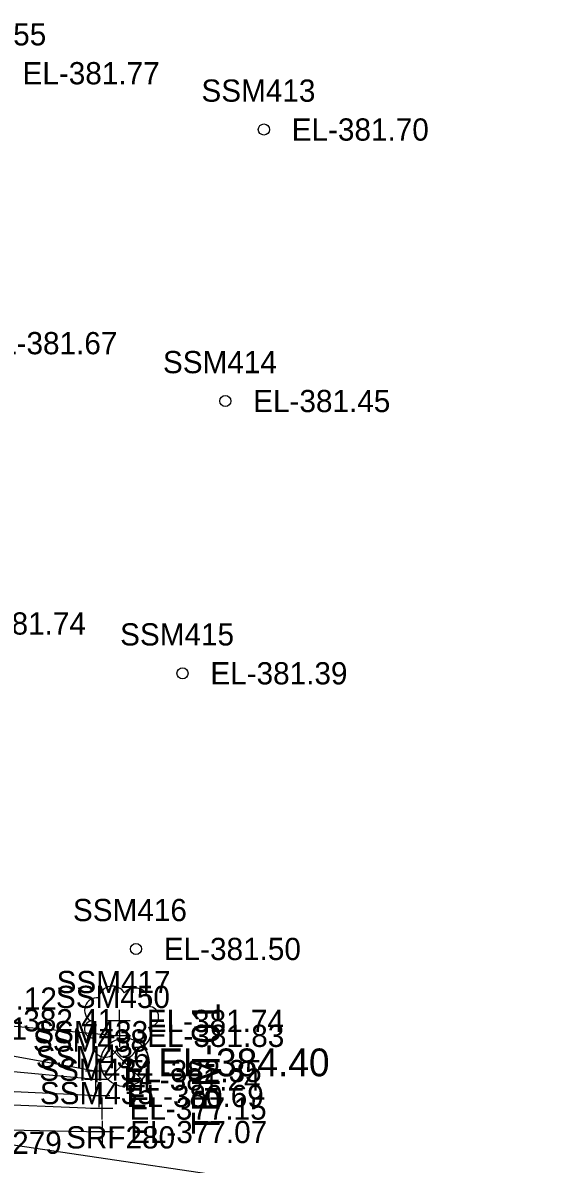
# Model space of a CAD drawing. Extents: x 1189978 to 1314812, y 571533 to 629339.
# Drawn here: x 1217598.3 to 1217693.4, y 620970.5 to 621175.8 of the extents above; entities that cross this region are included whole.
import ezdxf

# ---------------------------------------------------------------- set-up
doc = ezdxf.new("R2010")
doc.units = 0
for name, color, linetype in [('SURVEY - CONTROL - Points - Elevations', 7, 'Continuous'), ('SURVEY - CONTROL with Text', 7, 'Continuous'), ('SURVEY - DTM - Breaklines', 7, 'Continuous'), ('SURVEY - DTM - Breaklines - Points - Elevations', 7, 'Continuous'), ('SURVEY - DTM - Breaklines - Points - Locators', 7, 'Continuous'), ('SURVEY - DTM - Breaklines - Points - Numbers', 7, 'Continuous'), ('SURVEY - DTM - Spot Points - Elevations', 7, 'Continuous'), ('SURVEY - DTM - Spot Points - Locators', 7, 'Continuous'), ('SURVEY - DTM - Spot Points - Point Numbers', 7, 'Continuous'), ('SURVEY - PROPERTY - Property Lines', 7, 'Continuous'), ('SURVEY - VEGETATION - Features - Points - Elevations', 7, 'Continuous'), ('SURVEY - VEGETATION - Features - Points - Locators', 7, 'Continuous'), ('SURVEY - VEGETATION - Features - Points - Numbers', 7, 'Continuous'), ('SURVEY - VEGETATION - Features with Text', 7, 'Continuous')]:
    doc.layers.add(name, color=color, linetype=linetype)

msp = doc.modelspace()

# ---------------------------------------------------------------- linework, layer by layer
at = {"layer": 'SURVEY - CONTROL with Text'}
for p, q in [((1217613.54, 620991.87), (1217616.62, 620988.79)), ((1217616.62, 620988.79), (1217619.7, 620991.88)), ((1217613.55, 620985.73), (1217616.62, 620988.79)), ((1217616.62, 620988.79), (1217619.69, 620985.72))]:
    msp.add_line(p, q, dxfattribs=at)
for points in [[(1217613.55, 620991.86), (1217616.62, 620988.79), (1217613.56, 620985.74), (1217613.31, 620985.99), (1217613.06, 620986.32), (1217612.9, 620986.56), (1217612.73, 620986.88), (1217612.58, 620987.21), (1217612.48, 620987.49), (1217612.41, 620987.75), (1217612.35, 620988.04), (1217612.3, 620988.33), (1217612.28, 620988.59), (1217612.28, 620988.92), (1217612.3, 620989.19), (1217612.32, 620989.43), (1217612.36, 620989.63), (1217612.41, 620989.86), (1217612.49, 620990.13), (1217612.56, 620990.34), (1217612.65, 620990.57), (1217612.83, 620990.92), (1217613.03, 620991.25), (1217613.31, 620991.61)], [(1217619.69, 620991.86), (1217616.62, 620988.79), (1217619.69, 620985.72), (1217619.88, 620985.92), (1217620.11, 620986.19), (1217620.33, 620986.53), (1217620.48, 620986.78), (1217620.66, 620987.18), (1217620.77, 620987.47), (1217620.85, 620987.76), (1217620.9, 620987.99), (1217620.95, 620988.32), (1217620.97, 620988.57), (1217620.98, 620988.88), (1217620.96, 620989.18), (1217620.93, 620989.4), (1217620.89, 620989.67), (1217620.84, 620989.87), (1217620.77, 620990.12), (1217620.64, 620990.48), (1217620.54, 620990.69), (1217620.43, 620990.9), (1217620.22, 620991.25), (1217619.97, 620991.58)]]:
    msp.add_lwpolyline(points, close=True, dxfattribs=at)
msp.add_circle((1217616.63, 620988.8), 4.35, dxfattribs=at)
at = {"layer": 'SURVEY - DTM - Breaklines'}
for points in [[(1217505.41, 621014.24), (1217516.99, 621012.37), (1217518.09, 621005.1), (1217531.46, 621005.05), (1217569.34, 620994.87), (1217611.56, 620987.23)], [(1217508.49, 621010.32), (1217511.86, 621009.77), (1217513.63, 621003.75), (1217524.95, 620995.72), (1217565.78, 620982.39), (1217612.46, 620980.49)], [(1217611.95, 620982.75), (1217567.42, 620984.85), (1217526.98, 620996.85), (1217516.07, 621003.42), (1217514.47, 621008.39), (1217511.86, 621009.77)], [(1217611.37, 620985.73), (1217567.67, 620989.82), (1217529.71, 621000.21), (1217516.95, 621003.56)], [(1217509.63, 621001.3), (1217509.95, 621001.87), (1217523.3, 620992.1), (1217564.68, 620977.32), (1217612.57, 620976.27)]]:
    msp.add_lwpolyline(points, dxfattribs=at)
at = {"layer": 'SURVEY - DTM - Breaklines - Points - Locators'}
for p, q in [((1217611.56, 620989.23), (1217611.56, 620985.23)), ((1217613.56, 620987.23), (1217609.56, 620987.23)), ((1217611.37, 620987.73), (1217611.37, 620983.73)), ((1217613.37, 620985.73), (1217609.37, 620985.73)), ((1217611.95, 620984.75), (1217611.95, 620980.75)), ((1217613.95, 620982.75), (1217609.95, 620982.75)), ((1217612.46, 620982.49), (1217612.46, 620978.49)), ((1217614.46, 620980.49), (1217610.46, 620980.49)), ((1217612.57, 620978.27), (1217612.57, 620974.27)), ((1217614.57, 620976.27), (1217610.57, 620976.27))]:
    msp.add_line(p, q, dxfattribs=at)
at = {"layer": 'SURVEY - DTM - Spot Points - Locators'}
for centre in [(1217641.65, 621156.61), (1217634.72, 621107.77), (1217627.01, 621058.79), (1217618.63, 621009.2)]:
    msp.add_circle(centre, 1, dxfattribs=at)
at = {"layer": 'SURVEY - PROPERTY - Property Lines'}
msp.add_line((1217486.83, 620990.13), (1218812.31, 620794.77), dxfattribs=at)
at = {"layer": 'SURVEY - VEGETATION - Features - Points - Locators'}
for p, q in [((1217615.58, 620998.25), (1217615.58, 620994.25)), ((1217617.58, 620996.25), (1217613.58, 620996.25)), ((1217615.64, 620995.57), (1217615.64, 620991.57)), ((1217617.64, 620993.57), (1217613.64, 620993.57))]:
    msp.add_line(p, q, dxfattribs=at)
at = {"layer": 'SURVEY - VEGETATION - Features with Text'}
msp.add_lwpolyline([(1217602.67, 620954.84), (1217559.6, 620962.1), (1217546.12, 620967.76), (1217551.18, 620997.98), (1217585.03, 620996.37), (1217615.64, 620993.57)], dxfattribs=at)
msp.add_circle((1217615.68, 620996.29), 0.0783, dxfattribs=at)
for centre, radius, start, end in [((1217614.4, 620999.94), 2.56, 31.9683, 169.4925), ((1217618.48, 620999.61), 2.54, 342.8641, 138.7026), ((1217611.62, 620998.18), 2.24, 82.9155, 239.7044), ((1217620.84, 620996.99), 1.87, 273.117, 88.1173), ((1217610.89, 620994.75), 1.54, 105.0317, 283.7773), ((1217618.85, 620993.92), 2.41, 262.9581, 29.8037), ((1217613.09, 620991.98), 2.24, 145.0523, 338.472), ((1217616.86, 620991.38), 1.7, 187.671, 4.9902)]:
    msp.add_arc(centre, radius, start, end, dxfattribs=at)

# ---------------------------------------------------------------- texts
at = {"layer": 'SURVEY - CONTROL - Points - Elevations'}
msp.add_text('EL-384.40', height=5, dxfattribs=at).set_placement((1217622.62, 620986.29))
at = {"layer": 'SURVEY - CONTROL with Text'}
msp.add_text('TBM-01', height=5, rotation=90, dxfattribs=at).set_placement((1217633.7, 620975.81))
at = {"layer": 'SURVEY - DTM - Breaklines - Points - Elevations'}
for s, p in [('EL-382.71', (1217574.34, 620992.87)), ('EL-382.35', (1217616.56, 620985.23)), ('EL-381.24', (1217616.37, 620983.73)), ('EL-380.69', (1217616.95, 620980.75)), ('EL-377.15', (1217617.46, 620978.49)), ('EL-377.07', (1217617.57, 620974.27))]:
    msp.add_text(s, height=4, dxfattribs=at).set_placement(p)
at = {"layer": 'SURVEY - DTM - Breaklines - Points - Numbers'}
for s, p in [('SSM433', (1217600.32, 620992.23)), ('SSM438', (1217600.08, 620990.73)), ('SSM436', (1217600.6, 620987.75)), ('SSM434', (1217601.22, 620985.49)), ('SSM435', (1217601.33, 620981.27)), ('SRF280', (1217606.05, 620973.3)), ('SRF279', (1217585.65, 620972.34))]:
    msp.add_text(s, height=4, dxfattribs=at).set_placement(p)
at = {"layer": 'SURVEY - DTM - Spot Points - Elevations'}
for s, p in [('EL-381.77', (1217598.21, 621164.74)), ('EL-381.70', (1217646.65, 621154.61)), ('EL-381.67', (1217590.6, 621116.18)), ('EL-381.45', (1217639.72, 621105.77)), ('EL-381.74', (1217584.94, 621065.75)), ('EL-381.39', (1217632.01, 621056.79)), ('EL-381.50', (1217623.63, 621007.2)), ('EL-382.12', (1217579.72, 620998.27))]:
    msp.add_text(s, height=4, dxfattribs=at).set_placement(p)
at = {"layer": 'SURVEY - DTM - Spot Points - Point Numbers'}
for s, p in [('SSM355', (1217581.97, 621171.74)), ('SSM413', (1217630.41, 621161.61)), ('SSM414', (1217623.48, 621112.77)), ('SSM415', (1217615.77, 621063.79)), ('SSM416', (1217607.28, 621014.2))]:
    msp.add_text(s, height=4, dxfattribs=at).set_placement(p)
at = {"layer": 'SURVEY - VEGETATION - Features - Points - Elevations'}
for s, p in [('EL-382.41', (1217590.03, 620994.37)), ('EL-381.74', (1217620.58, 620994.25)), ('EL-381.83', (1217620.64, 620991.57))]:
    msp.add_text(s, height=4, dxfattribs=at).set_placement(p)
at = {"layer": 'SURVEY - VEGETATION - Features - Points - Numbers'}
for s, p in [('SSM417', (1217604.34, 621001.25)), ('SSM450', (1217604.22, 620998.57))]:
    msp.add_text(s, height=4, dxfattribs=at).set_placement(p)

doc.saveas('drawing.dxf')
